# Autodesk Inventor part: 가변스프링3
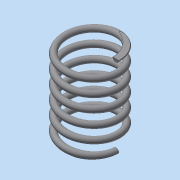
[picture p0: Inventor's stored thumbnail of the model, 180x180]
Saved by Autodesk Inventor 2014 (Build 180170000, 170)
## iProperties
Created: 2023-01
Part Number: 가변스프링3
Material: 일반
Document SubType Name: Modeling
Designer: dg
Density: 1 g/cm^3
Appearance: 기본값
Author: dg
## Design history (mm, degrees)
sketch "스케치1"
  geometry: L1 (0, 0)-(0, 26.33); L2 (0, 0)-(8.5, 0); L3 (0, 26.33)-(8.5, 26.33); C1 r 1 at (8.5, 0)
  constraints: 6 end point, 1 centre point, 1 coincident, 1 parallel, 1 perpendicular, 1 vertical, 1 vertical alignment
  dimensions: "d0" = 26.33013 distance of L1.start L1.end (derived); "d1" = 8.5 distance of L1.start L2.end; "d2" = 2 diameter of C1
feature "코일1" pitch "d3" = 10; turns "d5" = 6; dims "d4" = 26.33013 (= d0), "d6" = 0, angle "d7" = 90 deg, angle "d8" = 90 deg, "d9" = 0, "d10" = 0
node "작업 평면1"
node "작업 평면2"
feature "분할1"
feature "분할2"
node "솔리드1"
other parameters: "d11" = 0, "d12" = 0
